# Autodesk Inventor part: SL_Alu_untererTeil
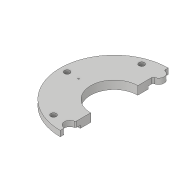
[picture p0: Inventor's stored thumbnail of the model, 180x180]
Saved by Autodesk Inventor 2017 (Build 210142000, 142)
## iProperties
Part Number: SL_Alu_untererTeil
Material: Generisch
Document SubType Name: Modeling
Designer: gabriel
Density: 1 g/cm^3
Appearance: Vorgabe
Author: gabriel
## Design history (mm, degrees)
sketch "Skizze1"
  geometry: L1 (-3.9, 0)-(23.4, 0) reference; L2 (0, -3.6)-(0, 0.6) reference; L3 (8.5, 0)-(19.5, 0); L4 (19.5, 0)-(19.5, -2); L5 (19.5, -2)-(12.25, -2); L6 (12.25, -2)-(12.25, -3); L7 (12.25, -3)-(8.5, -3); L8 (8.5, -3)-(8.5, 0); L9 (8.5, 0)-(9, 0); 1 further point
  constraints: 14 end point, 1 collinear, 1 horizontal, 1 parallel, 1 perpendicular
  dimensions: "d0" = 8.5 distance of point (0, 0) L3.start; "d1" = 11 distance between parallel lines of L8 L4; "d2" = 3.75 distance of L6.end L7.end; "d4" = 2 distance of L3.end L4.end; "d5" = 1 distance of L5.end L6.end
revolve "Umdrehung1" sketch "Skizze1" stored, may be unused: angle "d3" = 90 deg
sketch "Skizze4"
  geometry: L1 (27.3, 0)-(-27.3, 0) reference; L2 (0, -27.3)-(0, 27.3) reference; C1 r 1 at (-15.905, -6); C2 r 1 at (0, -17); C3 r 1 at (15.905, -6); 1 further point
  constraints: 3 centre point, 1 point on line
  dimensions: "d10" = 15.905 distance from line of L2 C1.centre; "d11" = 15.905 distance from line of L2 C3.centre; "d12" = 6 distance from line of L1 C3.centre; "d13" = 6 distance from line of L1 C1.centre; "d14" = 17 distance from line of L1 C2.centre; "d15" = 2 diameter of C1; "d16" = 2 diameter of C2; "d17" = 2 diameter of C3
extrude "Extrusion2" cut sketch "Skizze4" distance "d18" = 3; taper "d19" = 0 deg
sketch "Skizze5"
  geometry: L1 (0, -31)-(0, 32) reference; L2 (-28.2, 0)-(32.7, 0) reference; L3 (0, 23)-(24, 23); L4 (24, 23)-(24, -22); L5 (24, -22)-(0, -22); L6 (0, -22)-(0, 23); 1 further point
  constraints: 8 end point, 2 parallel, 1 horizontal, 1 perpendicular, 1 point on line
extrude "Extrusion3" cut sketch "Skizze5" stored distance "d20" = 3; taper "d21" = 0 deg
sketch "Skizze6"
  geometry: L1 (0, -27.3)-(0, 27.3) reference; L2 (-23.8, 0)-(6.3, 0) reference; L3 (0, 19.5)-(0, 12.25) reference; L4 (0, -19.5)-(0, -8.5) reference; L5 (0, 18)-(0, 14); L6 (0, 8.5)-(0, 19.5) reference; A1 r 2 centre (0, 16) between (0, 14) and (0, 18); 4 further points
  constraints: 3 point on line, 2 end point, 2 midpoint, 2 point on circle, 1 centre point, 1 coincident, 1 symmetric about line
  dimensions: "d22" = 16 distance from line of L2 point (0, 16); "d23" = 4 diameter of A1
extrude "Extrusion4" join sketch "Skizze6" stored distance "d24" = 3; taper "d25" = 0 deg
fillet "Rundung1" dims "d26" = 0.5
fillet "Rundung2" dims "d27" = 0.5
sketch "Skizze7"
  geometry: L1 (0, -27.3)-(0, 27.3) reference; L2 (-23.8, 0)-(6.3, 0) reference; 2 further points
  constraints: 1 point on line
  dimensions: "d28" = 16 distance from line of L2 point (0, -16)
hole "Bohrung1" sketch "Skizze7" at (0, -16) diameter "d29" = 4; stored, may be unused: countersink angle "d33" = 90 deg, drill point angle "d35" = 118 deg; dims "d30" = 6, "d31" = 4, "d32" = 2, "d34" = 8
fillet "Rundung3" dims "d36" = 0.5
fillet "Rundung4" dims "d37" = 0.5
sketch "Skizze8"
  geometry: L1 (0, -27.3)-(0, 27.3) reference; L2 (23.8, 0)-(-6.3, 0) reference; 2 further points
  constraints: 1 point on line
  dimensions: "d38" = 12.875 distance from line of L1 point (12.875, 0)
hole "Bohrung2" sketch "Skizze8" at (12.875, 0) diameter "d39" = 0.5; stored, may be unused: countersink angle "d43" = 90 deg, drill point angle "d45" = 118 deg; dims "d40" = 6, "d41" = 4, "d42" = 2, "d44" = 2
node "Volumenkörper1"
